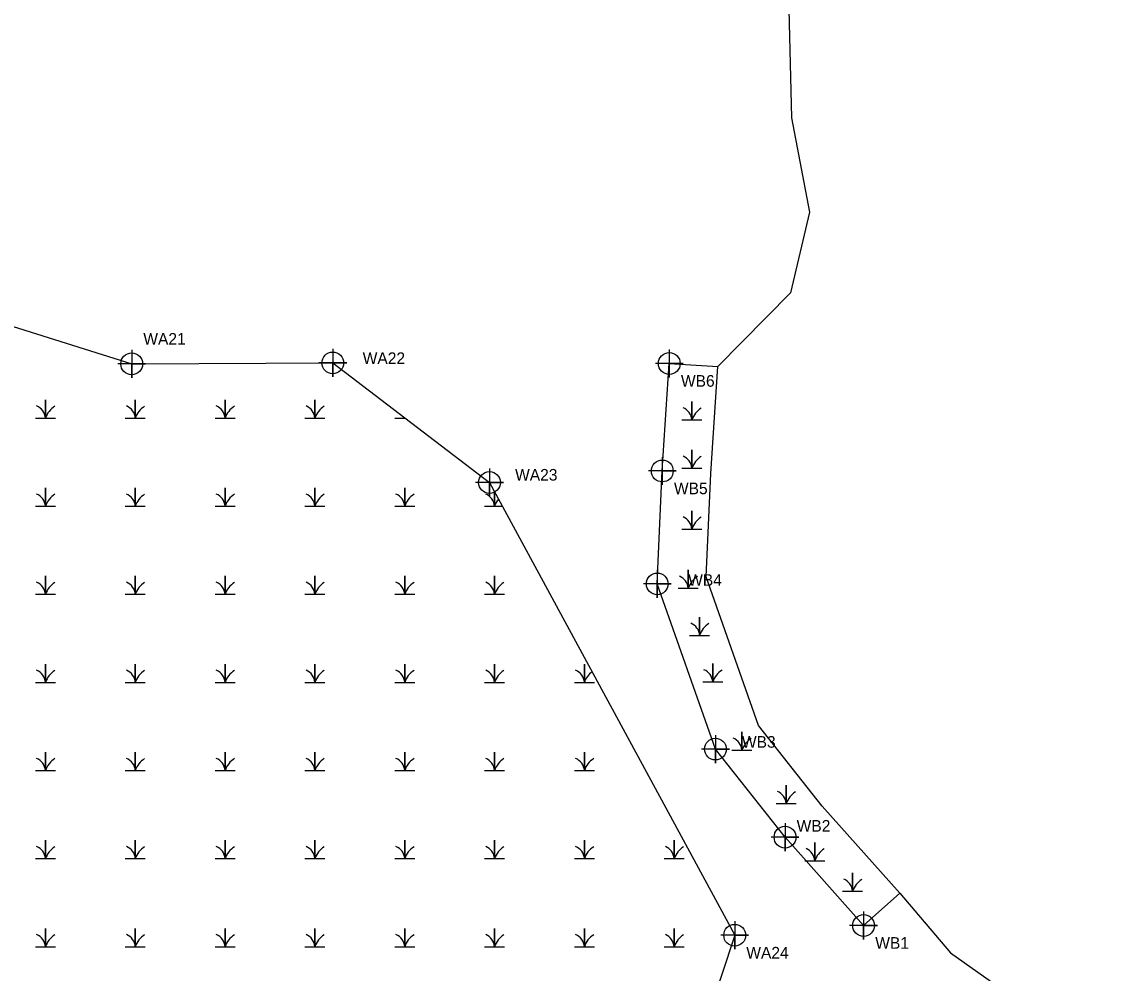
# Model space of a CAD drawing. Extents: x 2603618 to 2605510, y 618189 to 619022.
# Drawn here: x 2603915.3 to 2604151.1, y 618353.1 to 618557.6 of the extents above; entities that cross this region are included whole.
import ezdxf

# ---------------------------------------------------------------- set-up
doc = ezdxf.new("R2010")
doc.units = 0
for name, color, linetype in [('Exist Environmental Wetland Boundary', 7, 'Continuous'), ('Exist Environmental Wetland Boundary Cogo Comment', 7, 'Continuous'), ('Exist Environmental Wetland Boundary Cogo Point CELL', 7, 'Continuous'), ('Exist Hydro Jurisdictional Stream or Body of Water Mitigable', 7, 'Continuous'), ('Exist Hydro Swamp or Marsh', 7, 'Continuous')]:
    doc.layers.add(name, color=color, linetype=linetype)

# ---------------------------------------------------------------- blocks, each defined once
blk = doc.blocks.new('Exist Hydro Swamp or Marsh')
at = {"layer": 'Exist Hydro Swamp or Marsh'}
blk.add_line((0, 0), (0, 0), dxfattribs=at)
blk.add_lwpolyline([(-0.043, -0.0357), (0, -0.0357), (0, 0.0432), (0, -0.0357), (0.043, -0.0357)], dxfattribs=at)
for centre, radius, start, end in [((-0.0613, -0.0401), 0.0615, 4.1403, 67.535), ((0.0912, -0.066), 0.0961, 122.1274, 161.6222)]:
    blk.add_arc(centre, radius, start, end, dxfattribs=at)

msp = doc.modelspace()

# ---------------------------------------------------------------- linework, layer by layer
at = {"layer": 'Exist Environmental Wetland Boundary'}
for p, q in [((2604054.44, 618484.18), (2604064.84, 618483.51)), ((2604096.2, 618363.33), (2604103.98, 618370.25))]:
    msp.add_line(p, q, dxfattribs=at)
for points in [[(2603897.92, 618497.01), (2603938.9, 618484.11), (2603982.11, 618484.31), (2604015.8, 618458.6), (2604068.49, 618361.23), (2604056.99, 618326.31), (2604044.69, 618262)], [(2604096.2, 618363.33), (2604079.31, 618382.32), (2604064.35, 618401.27), (2604051.86, 618436.79), (2604052.94, 618461.07), (2604054.44, 618484.18)], [(2604103.98, 618370.25), (2604087.3, 618389.02), (2604073.6, 618406.36), (2604062.36, 618438.34), (2604063.34, 618460.5), (2604064.84, 618483.51)], [(2603918.23, 618472.44), (2603920.38, 618472.44), (2603920.38, 618476.38), (2603920.38, 618472.44), (2603922.53, 618472.44)], [(2603937.53, 618472.44), (2603939.68, 618472.44), (2603939.68, 618476.38), (2603939.68, 618472.44), (2603941.83, 618472.44)], [(2603956.83, 618472.44), (2603958.98, 618472.44), (2603958.98, 618476.38), (2603958.98, 618472.44), (2603961.13, 618472.44)], [(2603976.13, 618472.44), (2603978.28, 618472.44), (2603978.28, 618476.38), (2603978.28, 618472.44), (2603980.43, 618472.44)], [(2603995.43, 618472.44), (2603997.58, 618472.44), (2603997.58, 618472.5)], [(2603997.58, 618472.5), (2603997.58, 618472.44), (2603997.67, 618472.44)], [(2603918.23, 618453.49), (2603920.38, 618453.49), (2603920.38, 618457.44), (2603920.38, 618453.49), (2603922.53, 618453.49)], [(2603937.53, 618453.49), (2603939.68, 618453.49), (2603939.68, 618457.44), (2603939.68, 618453.49), (2603941.83, 618453.49)], [(2603956.83, 618453.49), (2603958.98, 618453.49), (2603958.98, 618457.44), (2603958.98, 618453.49), (2603961.13, 618453.49)], [(2603976.13, 618453.49), (2603978.28, 618453.49), (2603978.28, 618457.44), (2603978.28, 618453.49), (2603980.43, 618453.49)], [(2603995.43, 618453.49), (2603997.58, 618453.49), (2603997.58, 618457.44), (2603997.58, 618453.49), (2603999.73, 618453.49)], [(2604014.73, 618453.49), (2604016.88, 618453.49), (2604016.88, 618456.52)], [(2604016.88, 618456.52), (2604016.88, 618453.49), (2604018.56, 618453.49)], [(2603918.23, 618434.55), (2603920.38, 618434.55), (2603920.38, 618438.49), (2603920.38, 618434.55), (2603922.53, 618434.55)], [(2603937.53, 618434.55), (2603939.68, 618434.55), (2603939.68, 618438.49), (2603939.68, 618434.55), (2603941.83, 618434.55)], [(2603956.83, 618434.55), (2603958.98, 618434.55), (2603958.98, 618438.49), (2603958.98, 618434.55), (2603961.13, 618434.55)], [(2603976.13, 618434.55), (2603978.28, 618434.55), (2603978.28, 618438.49), (2603978.28, 618434.55), (2603980.43, 618434.55)], [(2603995.43, 618434.55), (2603997.58, 618434.55), (2603997.58, 618438.49), (2603997.58, 618434.55), (2603999.73, 618434.55)], [(2604014.73, 618434.55), (2604016.88, 618434.55), (2604016.88, 618438.49), (2604016.88, 618434.55), (2604019.04, 618434.55)], [(2603918.23, 618415.6), (2603920.38, 618415.6), (2603920.38, 618419.55), (2603920.38, 618415.6), (2603922.53, 618415.6)], [(2603937.53, 618415.6), (2603939.68, 618415.6), (2603939.68, 618419.55), (2603939.68, 618415.6), (2603941.83, 618415.6)], [(2603956.83, 618415.6), (2603958.98, 618415.6), (2603958.98, 618419.55), (2603958.98, 618415.6), (2603961.13, 618415.6)], [(2603976.13, 618415.6), (2603978.28, 618415.6), (2603978.28, 618419.55), (2603978.28, 618415.6), (2603980.43, 618415.6)], [(2603995.43, 618415.6), (2603997.58, 618415.6), (2603997.58, 618419.55), (2603997.58, 618415.6), (2603999.73, 618415.6)], [(2604014.73, 618415.6), (2604016.88, 618415.6), (2604016.88, 618419.55), (2604016.88, 618415.6), (2604019.04, 618415.6)], [(2604034.04, 618415.6), (2604036.19, 618415.6), (2604036.19, 618419.55), (2604036.19, 618415.6), (2604038.34, 618415.6)], [(2603918.23, 618396.66), (2603920.38, 618396.66), (2603920.38, 618400.6), (2603920.38, 618396.66), (2603922.53, 618396.66)], [(2603937.53, 618396.66), (2603939.68, 618396.66), (2603939.68, 618400.6), (2603939.68, 618396.66), (2603941.83, 618396.66)], [(2603956.83, 618396.66), (2603958.98, 618396.66), (2603958.98, 618400.6), (2603958.98, 618396.66), (2603961.13, 618396.66)], [(2603976.13, 618396.66), (2603978.28, 618396.66), (2603978.28, 618400.6), (2603978.28, 618396.66), (2603980.43, 618396.66)], [(2603995.43, 618396.66), (2603997.58, 618396.66), (2603997.58, 618400.6), (2603997.58, 618396.66), (2603999.73, 618396.66)], [(2604014.73, 618396.66), (2604016.88, 618396.66), (2604016.88, 618400.6), (2604016.88, 618396.66), (2604019.04, 618396.66)], [(2604034.04, 618396.66), (2604036.19, 618396.66), (2604036.19, 618400.6), (2604036.19, 618396.66), (2604038.34, 618396.66)], [(2603918.23, 618377.71), (2603920.38, 618377.71), (2603920.38, 618381.66), (2603920.38, 618377.71), (2603922.53, 618377.71)], [(2603937.53, 618377.71), (2603939.68, 618377.71), (2603939.68, 618381.66), (2603939.68, 618377.71), (2603941.83, 618377.71)], [(2603956.83, 618377.71), (2603958.98, 618377.71), (2603958.98, 618381.66), (2603958.98, 618377.71), (2603961.13, 618377.71)], [(2603976.13, 618377.71), (2603978.28, 618377.71), (2603978.28, 618381.66), (2603978.28, 618377.71), (2603980.43, 618377.71)], [(2603995.43, 618377.71), (2603997.58, 618377.71), (2603997.58, 618381.66), (2603997.58, 618377.71), (2603999.73, 618377.71)], [(2604014.73, 618377.71), (2604016.88, 618377.71), (2604016.88, 618381.66), (2604016.88, 618377.71), (2604019.04, 618377.71)], [(2604034.04, 618377.71), (2604036.19, 618377.71), (2604036.19, 618381.66), (2604036.19, 618377.71), (2604038.34, 618377.71)], [(2604053.34, 618377.71), (2604055.49, 618377.71), (2604055.49, 618381.66), (2604055.49, 618377.71), (2604057.64, 618377.71)], [(2603918.23, 618358.76), (2603920.38, 618358.76), (2603920.38, 618362.71), (2603920.38, 618358.76), (2603922.53, 618358.76)], [(2603937.53, 618358.76), (2603939.68, 618358.76), (2603939.68, 618362.71), (2603939.68, 618358.76), (2603941.83, 618358.76)], [(2603956.83, 618358.76), (2603958.98, 618358.76), (2603958.98, 618362.71), (2603958.98, 618358.76), (2603961.13, 618358.76)], [(2603976.13, 618358.76), (2603978.28, 618358.76), (2603978.28, 618362.71), (2603978.28, 618358.76), (2603980.43, 618358.76)], [(2603995.43, 618358.76), (2603997.58, 618358.76), (2603997.58, 618362.71), (2603997.58, 618358.76), (2603999.73, 618358.76)], [(2604014.73, 618358.76), (2604016.88, 618358.76), (2604016.88, 618362.71), (2604016.88, 618358.76), (2604019.04, 618358.76)], [(2604034.04, 618358.76), (2604036.19, 618358.76), (2604036.19, 618362.71), (2604036.19, 618358.76), (2604038.34, 618358.76)], [(2604053.34, 618358.76), (2604055.49, 618358.76), (2604055.49, 618362.71), (2604055.49, 618358.76), (2604057.64, 618358.76)]]:
    msp.add_lwpolyline(points, dxfattribs=at)
for centre, radius, start, end in [((2603917.31, 618472.21), 3.07, 4.1403, 67.535), ((2603924.94, 618470.92), 4.81, 122.1274, 161.6222), ((2603936.62, 618472.21), 3.07, 4.1403, 67.535), ((2603944.24, 618470.92), 4.81, 122.1274, 161.6222), ((2603955.92, 618472.21), 3.07, 4.1403, 67.535), ((2603963.54, 618470.92), 4.81, 122.1274, 161.6222), ((2603975.22, 618472.21), 3.07, 4.1403, 67.535), ((2603982.84, 618470.92), 4.81, 122.1274, 161.6222), ((2603994.52, 618472.21), 3.07, 4.1403, 5.4037), ((2604002.14, 618470.92), 4.81, 160.9895, 161.6222), ((2603917.31, 618453.27), 3.07, 4.1403, 67.535), ((2603924.94, 618451.98), 4.81, 122.1274, 161.6222), ((2603936.62, 618453.27), 3.07, 4.1403, 67.535), ((2603944.24, 618451.98), 4.81, 122.1274, 161.6222), ((2603955.92, 618453.27), 3.07, 4.1403, 67.535), ((2603963.54, 618451.98), 4.81, 122.1274, 161.6222), ((2603975.22, 618453.27), 3.07, 4.1403, 67.535), ((2603982.84, 618451.98), 4.81, 122.1274, 161.6222), ((2603994.52, 618453.27), 3.07, 4.1403, 67.535), ((2604002.14, 618451.98), 4.81, 122.1274, 161.6222), ((2604013.82, 618453.27), 3.07, 4.1403, 67.535), ((2604021.45, 618451.98), 4.81, 140.6115, 161.6222), ((2603917.31, 618434.32), 3.07, 4.1403, 67.535), ((2603924.94, 618433.03), 4.81, 122.1274, 161.6222), ((2603936.62, 618434.32), 3.07, 4.1403, 67.535), ((2603944.24, 618433.03), 4.81, 122.1274, 161.6222), ((2603955.92, 618434.32), 3.07, 4.1403, 67.535), ((2603963.54, 618433.03), 4.81, 122.1274, 161.6222), ((2603975.22, 618434.32), 3.07, 4.1403, 67.535), ((2603982.84, 618433.03), 4.81, 122.1274, 161.6222), ((2603994.52, 618434.32), 3.07, 4.1403, 67.535), ((2604002.14, 618433.03), 4.81, 122.1274, 161.6222), ((2604013.82, 618434.32), 3.07, 4.1403, 67.535), ((2604021.45, 618433.03), 4.81, 122.1274, 161.6222), ((2603917.31, 618415.38), 3.07, 4.1403, 67.535), ((2603924.94, 618414.09), 4.81, 122.1274, 161.6222), ((2603936.62, 618415.38), 3.07, 4.1403, 67.535), ((2603944.24, 618414.09), 4.81, 122.1274, 161.6222), ((2603955.92, 618415.38), 3.07, 4.1403, 67.535), ((2603963.54, 618414.09), 4.81, 122.1274, 161.6222), ((2603975.22, 618415.38), 3.07, 4.1403, 67.535), ((2603982.84, 618414.09), 4.81, 122.1274, 161.6222), ((2603994.52, 618415.38), 3.07, 4.1403, 67.535), ((2604002.14, 618414.09), 4.81, 122.1274, 161.6222), ((2604013.82, 618415.38), 3.07, 4.1403, 67.535), ((2604021.45, 618414.09), 4.81, 122.1274, 161.6222), ((2604033.12, 618415.38), 3.07, 4.1403, 67.535), ((2604040.75, 618414.09), 4.81, 127.4897, 161.6222), ((2603917.31, 618396.43), 3.07, 4.1403, 67.535), ((2603924.94, 618395.14), 4.81, 122.1274, 161.6222), ((2603936.62, 618396.43), 3.07, 4.1403, 67.535), ((2603944.24, 618395.14), 4.81, 122.1274, 161.6222), ((2603955.92, 618396.43), 3.07, 4.1403, 67.535), ((2603963.54, 618395.14), 4.81, 122.1274, 161.6222), ((2603975.22, 618396.43), 3.07, 4.1403, 67.535), ((2603982.84, 618395.14), 4.81, 122.1274, 161.6222), ((2603994.52, 618396.43), 3.07, 4.1403, 67.535), ((2604002.14, 618395.14), 4.81, 122.1274, 161.6222), ((2604013.82, 618396.43), 3.07, 4.1403, 67.535), ((2604021.45, 618395.14), 4.81, 122.1274, 161.6222), ((2604033.12, 618396.43), 3.07, 4.1403, 67.535), ((2604040.75, 618395.14), 4.81, 122.1274, 161.6222), ((2603917.31, 618377.49), 3.07, 4.1403, 67.535), ((2603924.94, 618376.19), 4.81, 122.1274, 161.6222), ((2603936.62, 618377.49), 3.07, 4.1403, 67.535), ((2603944.24, 618376.19), 4.81, 122.1274, 161.6222), ((2603955.92, 618377.49), 3.07, 4.1403, 67.535), ((2603963.54, 618376.19), 4.81, 122.1274, 161.6222), ((2603975.22, 618377.49), 3.07, 4.1403, 67.535), ((2603982.84, 618376.19), 4.81, 122.1274, 161.6222), ((2603994.52, 618377.49), 3.07, 4.1403, 67.535), ((2604002.14, 618376.19), 4.81, 122.1274, 161.6222), ((2604013.82, 618377.49), 3.07, 4.1403, 67.535), ((2604021.45, 618376.19), 4.81, 122.1274, 161.6222), ((2604033.12, 618377.49), 3.07, 4.1403, 67.535), ((2604040.75, 618376.19), 4.81, 122.1274, 161.6222), ((2604052.42, 618377.49), 3.07, 4.1403, 67.535), ((2604060.05, 618376.19), 4.81, 122.1274, 161.6222), ((2603917.31, 618358.54), 3.07, 4.1403, 67.535), ((2603924.94, 618357.25), 4.81, 122.1274, 161.6222), ((2603936.62, 618358.54), 3.07, 4.1403, 67.535), ((2603944.24, 618357.25), 4.81, 122.1274, 161.6222), ((2603955.92, 618358.54), 3.07, 4.1403, 67.535), ((2603963.54, 618357.25), 4.81, 122.1274, 161.6222), ((2603975.22, 618358.54), 3.07, 4.1403, 67.535), ((2603982.84, 618357.25), 4.81, 122.1274, 161.6222), ((2603994.52, 618358.54), 3.07, 4.1403, 67.535), ((2604002.14, 618357.25), 4.81, 122.1274, 161.6222), ((2604013.82, 618358.54), 3.07, 4.1403, 67.535), ((2604021.45, 618357.25), 4.81, 122.1274, 161.6222), ((2604033.12, 618358.54), 3.07, 4.1403, 67.535), ((2604040.75, 618357.25), 4.81, 122.1274, 161.6222), ((2604052.42, 618358.54), 3.07, 4.1403, 67.535), ((2604060.05, 618357.25), 4.81, 122.1274, 161.6222)]:
    msp.add_arc(centre, radius, start, end, dxfattribs=at)
at = {"layer": 'Exist Environmental Wetland Boundary Cogo Point CELL'}
for points in [[(2603938.9, 618487.11), (2603938.9, 618481.11), (2603938.9, 618484.11), (2603941.9, 618484.11), (2603935.9, 618484.11)], [(2603982.11, 618487.31), (2603982.11, 618481.31), (2603982.11, 618484.31), (2603985.11, 618484.31), (2603979.11, 618484.31)], [(2604054.44, 618487.18), (2604054.44, 618481.18), (2604054.44, 618484.18), (2604057.44, 618484.18), (2604051.44, 618484.18)], [(2604052.94, 618464.07), (2604052.94, 618458.07), (2604052.94, 618461.07), (2604055.94, 618461.07), (2604049.94, 618461.07)], [(2604015.8, 618461.6), (2604015.8, 618455.6), (2604015.8, 618458.6), (2604018.8, 618458.6), (2604012.8, 618458.6)], [(2604051.86, 618439.79), (2604051.86, 618433.79), (2604051.86, 618436.79), (2604054.86, 618436.79), (2604048.86, 618436.79)], [(2604064.35, 618404.27), (2604064.35, 618398.27), (2604064.35, 618401.27), (2604067.35, 618401.27), (2604061.35, 618401.27)], [(2604079.31, 618385.32), (2604079.31, 618379.32), (2604079.31, 618382.32), (2604082.31, 618382.32), (2604076.31, 618382.32)], [(2604096.2, 618366.33), (2604096.2, 618360.33), (2604096.2, 618363.33), (2604099.2, 618363.33), (2604093.2, 618363.33)], [(2604068.49, 618364.23), (2604068.49, 618358.23), (2604068.49, 618361.23), (2604071.49, 618361.23), (2604065.49, 618361.23)]]:
    msp.add_lwpolyline(points, dxfattribs=at)
for centre in [(2603938.9, 618484.11), (2603982.11, 618484.31), (2604054.44, 618484.18), (2604052.94, 618461.07), (2604015.8, 618458.6), (2604051.86, 618436.79), (2604064.35, 618401.27), (2604079.31, 618382.32), (2604068.49, 618361.23), (2604096.2, 618363.33)]:
    msp.add_circle(centre, 2.34, dxfattribs=at)
at = {"layer": 'Exist Hydro Jurisdictional Stream or Body of Water Mitigable'}
for points in [[(2604094.99, 618646.62), (2604085.5, 618630.9), (2604083.83, 618612.61), (2604079.88, 618569.09), (2604080.71, 618537.01), (2604084.58, 618516.73)], [(2604084.58, 618516.73), (2604080.48, 618499.41), (2604064.84, 618483.51)], [(2604103.98, 618370.25), (2604114.88, 618357.43), (2604134.24, 618343.76), (2604151.09, 618330.77)]]:
    msp.add_lwpolyline(points, dxfattribs=at)

# ---------------------------------------------------------------- block references
at = {"layer": 'Exist Hydro Swamp or Marsh', "xscale": 50, "yscale": 50}
for p in [(2604059.29, 618473.84), (2604059.29, 618463.43), (2604059.29, 618450.37), (2604058.5, 618437.63), (2604060.96, 618427.51), (2604063.77, 618417.49), (2604070.05, 618402.81), (2604079.56, 618391.34), (2604085.71, 618379.04), (2604093.81, 618372.48)]:
    msp.add_blockref('Exist Hydro Swamp or Marsh', p, dxfattribs=at)

# ---------------------------------------------------------------- texts
at = {"layer": 'Exist Environmental Wetland Boundary Cogo Comment'}
for s, p in [('WA21', (2603941.4, 618488.23)), ('WA22', (2603988.55, 618484.07)), ('WB6', (2604056.94, 618479.19)), ('WA23', (2604021.3, 618459)), ('WB5', (2604055.44, 618456.07)), ('WB4', (2604058.5, 618436.38)), ('WB3', (2604070.05, 618401.56)), ('WB2', (2604081.81, 618383.51)), ('WB1', (2604098.7, 618358.33)), ('WA24', (2604070.99, 618356.23))]:
    msp.add_text(s, height=2.5, dxfattribs=at).set_placement(p)

doc.saveas('drawing.dxf')
